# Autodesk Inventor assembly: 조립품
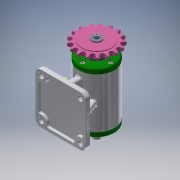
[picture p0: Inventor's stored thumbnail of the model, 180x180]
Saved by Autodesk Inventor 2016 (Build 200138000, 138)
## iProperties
Created: 2019-06
Part Number: 조립품
Material: 일반
Document SubType Name: Assembly
Designer: 605-12
Author: 605-12
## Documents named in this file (11)
- C:\Users\605-12\Desktop\490604V1020\조립품.iam
- C:\Users\605-12\Desktop\490604V1020\부품1.ipt
- C:\Users\605-12\Desktop\490604V1020\커버.ipt
- C:\Users\605-12\Desktop\490604V1020\베어링 6203.ipt
- C:\Users\605-12\Desktop\490604V1020\오일 실 17 30 5.ipt
- C:\Users\605-12\Desktop\490604V1020\축.ipt
- C:\Users\605-12\Desktop\490604V1020\키 4x4x12.ipt
- C:\Users\605-12\Desktop\490604V1020\스프로킷.ipt
- C:\Users\605-12\Desktop\490604V1020\볼트 M4.ipt
- C:\Users\605-12\Desktop\490604V1020\평와셔.ipt
- C:\Users\605-12\Desktop\490604V1020\스프링와셔.ipt
